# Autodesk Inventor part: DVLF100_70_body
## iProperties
Created: 2010-03
Part Number: DVLF100_70_body
Document SubType Name: Modeling
Designer: TB
Mass: 2195.3 g
Surface Area: 2630.8 cm^2
Volume: 2195.3 cm^3
Density: 1 g/cm^3
Author: TB
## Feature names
1. Kropp [Revolution]
2. Chamfer
3. Extrusion2
4. Hole1
5. Revolution2
6. Hole2
7. Fillet1
8. Extrusion3
9. Hole3
